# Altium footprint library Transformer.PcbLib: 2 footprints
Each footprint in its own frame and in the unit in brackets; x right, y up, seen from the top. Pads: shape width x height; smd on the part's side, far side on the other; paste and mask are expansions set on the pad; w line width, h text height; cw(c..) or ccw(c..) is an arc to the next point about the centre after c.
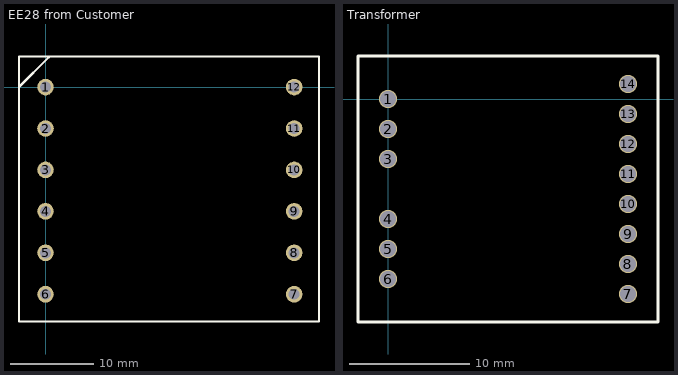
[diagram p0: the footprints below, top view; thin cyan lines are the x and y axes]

## EE28 from Customer [mm]
pads (12):
  round 2 hole 1.32: 1(0,0) 2(0,-5) 3(0,-10) 4(0,-15) 5(0,-20) 6(0,-25) 7(30,-25) 8(30,-20) 9(30,-15) 10(30,-10) 11(30,-5) 12(30,0)
Top Overlay:
  lines w0.254: -3.2,0 0.4,3.6 ; -3.2,-28.3 33,-28.3 33,3.7 -3.2,3.7 -3.2,-28.3
M5 Assembly Top:
  text ".Designator" at 0.516,-2.421 h1.02

## Transformer [mm]
pads (14):
  round 1.524 hole 1.32: 1(0,0) 2(0,-2.5) 3(0,-5) 4(0,-10) 5(0,-12.5) 6(0,-15) 7(20,-16.25) 8(20,-13.75) 9(20,-11.25) 10(20,-8.75) 11(20,-6.25) 12(20,-3.75) 13(20,-1.25) 14(20,1.25)
Top Overlay:
  lines w0.254: -2.5,-18.6 -2.5,3.6 22.5,3.6 22.5,-18.6 -2.5,-18.6
M5 Assembly Top:
  text ".Designator" at 0.516,-2.421 h1.02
